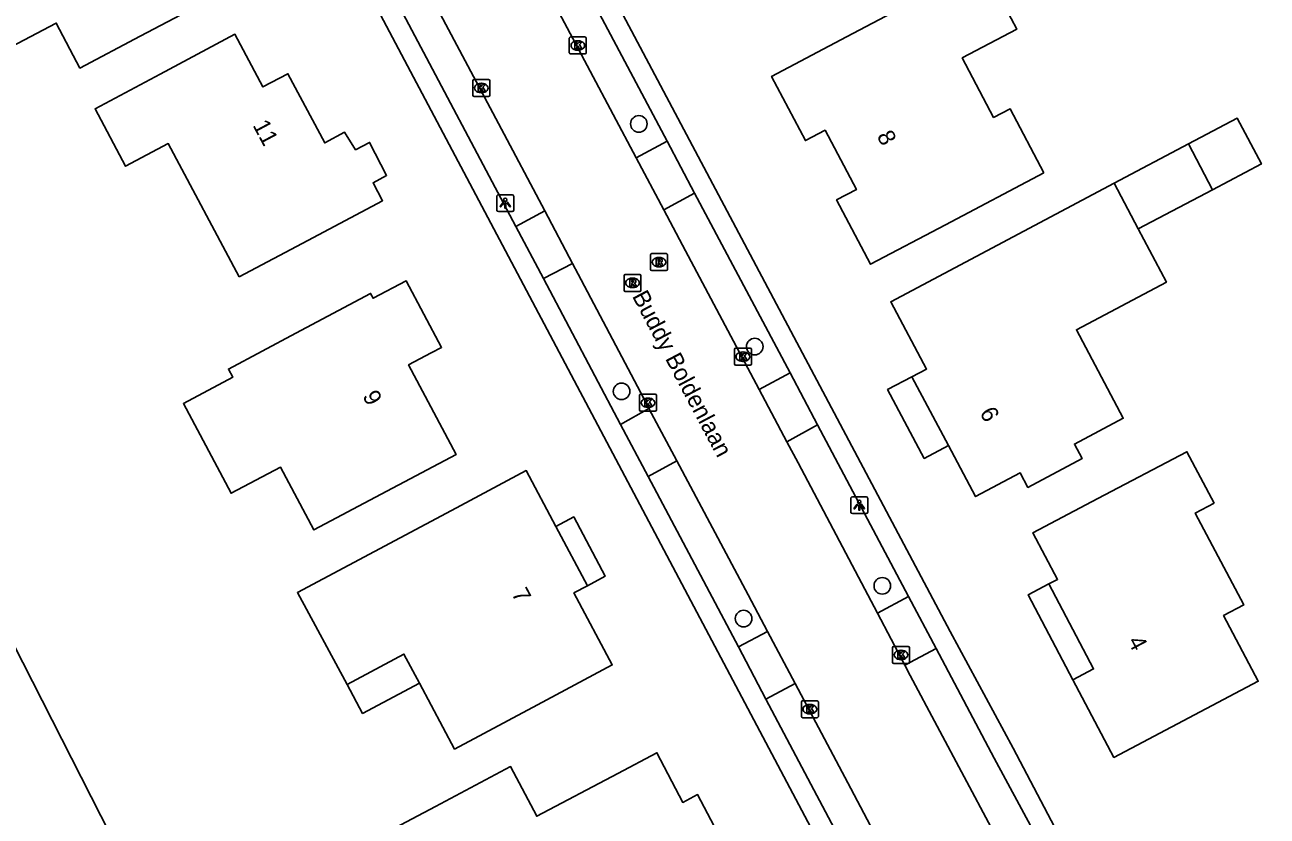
# Model space of a CAD drawing. Extents: x 160457 to 162082, y 388340 to 389736.
# Drawn here: x 160653.5 to 160726.7, y 389082.1 to 389128.7 of the extents above; entities that cross this region are included whole.
import ezdxf

# ---------------------------------------------------------------- set-up
doc = ezdxf.new("R2010")
doc.units = 0
for name, color, linetype in [('IMGEO_Boom', 7, 'Continuous'), ('IMGEO_Grasland_overig', 7, 'Continuous'), ('IMGEO_Hek', 7, 'Continuous'), ('IMGEO_Kolk', 7, 'Continuous'), ('IMGEO_Lichtpunt', 7, 'Continuous'), ('IMGEO_Openbare_ruimte_label', 7, 'Continuous'), ('IMGEO_Pand', 7, 'Continuous'), ('IMGEO_Pand_nummerreeks', 7, 'Continuous'), ('IMGEO_Pand_overbouw', 7, 'Continuous'), ('IMGEO_Rijbaan_lokaal_gesloten', 7, 'Continuous'), ('IMGEO_Rioolput', 7, 'Continuous'), ('IMGEO_Voetpad_open', 7, 'Continuous')]:
    doc.layers.add(name, color=color, linetype=linetype)

msp = doc.modelspace()

# ---------------------------------------------------------------- linework, layer by layer
at = {"layer": 'IMGEO_Boom'}
for centre in [(160689.681, 389122.893), (160696.514, 389109.757), (160688.66, 389107.12), (160704.034, 389095.651), (160695.854, 389093.718)]:
    msp.add_circle(centre, 0.489, dxfattribs=at)
at = {"layer": 'IMGEO_Grasland_overig'}
msp.add_lwpolyline([(160635.49, 389126.227), (160661.981, 389074.172), (160677.134, 389044.454)], dxfattribs=at)
at = {"layer": 'IMGEO_Hek'}
msp.add_lwpolyline([(160661.981, 389074.172), (160635.49, 389126.227), (160631.304, 389134.452)], dxfattribs=at)
at = {"layer": 'IMGEO_Kolk'}
for p, q in [((160685.58, 389127.091), (160685.58, 389127.943)), ((160685.655, 389128.017), (160686.507, 389128.017)), ((160686.068, 389127.797), (160686.093, 389127.797)), ((160686.581, 389127.943), (160686.581, 389127.091)), ((160686.507, 389127.017), (160685.655, 389127.017)), ((160686.091, 389127.237), (160686.066, 389127.237)), ((160679.891, 389124.581), (160679.891, 389125.433)), ((160679.966, 389125.507), (160680.818, 389125.507)), ((160680.892, 389125.433), (160680.892, 389124.581)), ((160680.402, 389124.727), (160680.377, 389124.727)), ((160680.379, 389125.287), (160680.404, 389125.287)), ((160680.818, 389124.507), (160679.966, 389124.507)), ((160695.314, 389108.738), (160695.314, 389109.59)), ((160695.389, 389109.664), (160696.241, 389109.664)), ((160695.802, 389109.444), (160695.827, 389109.444)), ((160696.315, 389109.59), (160696.315, 389108.738)), ((160696.241, 389108.664), (160695.389, 389108.664)), ((160695.825, 389108.884), (160695.8, 389108.884)), ((160689.716, 389106.021), (160689.716, 389106.873)), ((160689.791, 389106.947), (160690.643, 389106.947)), ((160690.204, 389106.727), (160690.229, 389106.727)), ((160690.717, 389106.873), (160690.717, 389106.021)), ((160690.643, 389105.947), (160689.791, 389105.947)), ((160690.227, 389106.167), (160690.202, 389106.167)), ((160704.638, 389091.15), (160704.638, 389092.002)), ((160704.713, 389092.076), (160705.565, 389092.076)), ((160705.126, 389091.856), (160705.151, 389091.856)), ((160705.639, 389092.002), (160705.639, 389091.15)), ((160705.565, 389091.076), (160704.713, 389091.076)), ((160705.149, 389091.296), (160705.124, 389091.296)), ((160699.263, 389087.949), (160699.263, 389088.801)), ((160699.338, 389088.875), (160700.19, 389088.875)), ((160700.264, 389088.801), (160700.264, 389087.949)), ((160699.774, 389088.095), (160699.749, 389088.095)), ((160699.751, 389088.655), (160699.776, 389088.655)), ((160700.19, 389087.875), (160699.338, 389087.875))]:
    msp.add_line(p, q, dxfattribs=at)
for points in [[(160685.58, 389127.091), (160685.58, 389127.943)], [(160685.655, 389128.017), (160686.507, 389128.017)], [(160685.901, 389127.717), (160686.024, 389127.717), (160686.024, 389127.566), (160686.154, 389127.717), (160686.318, 389127.717), (160686.172, 389127.566), (160686.325, 389127.317), (160686.173, 389127.317), (160686.088, 389127.481), (160686.024, 389127.414), (160686.024, 389127.317), (160685.901, 389127.317), (160685.901, 389127.717)], [(160686.581, 389127.943), (160686.581, 389127.091)], [(160686.507, 389127.017), (160685.655, 389127.017)], [(160679.891, 389124.581), (160679.891, 389125.433)], [(160679.966, 389125.507), (160680.818, 389125.507)], [(160680.892, 389125.433), (160680.892, 389124.581)], [(160680.212, 389125.207), (160680.335, 389125.207), (160680.335, 389125.056), (160680.465, 389125.207), (160680.629, 389125.207), (160680.483, 389125.056), (160680.636, 389124.807), (160680.484, 389124.807), (160680.399, 389124.971), (160680.335, 389124.904), (160680.335, 389124.807), (160680.212, 389124.807), (160680.212, 389125.207)], [(160680.818, 389124.507), (160679.966, 389124.507)], [(160695.314, 389108.738), (160695.314, 389109.59)], [(160695.389, 389109.664), (160696.241, 389109.664)], [(160695.635, 389109.364), (160695.758, 389109.364), (160695.758, 389109.213), (160695.888, 389109.364), (160696.052, 389109.364), (160695.906, 389109.213), (160696.059, 389108.964), (160695.907, 389108.964), (160695.822, 389109.128), (160695.758, 389109.061), (160695.758, 389108.964), (160695.635, 389108.964), (160695.635, 389109.364)], [(160696.315, 389109.59), (160696.315, 389108.738)], [(160696.241, 389108.664), (160695.389, 389108.664)], [(160689.716, 389106.021), (160689.716, 389106.873)], [(160689.791, 389106.947), (160690.643, 389106.947)], [(160690.037, 389106.647), (160690.16, 389106.647), (160690.16, 389106.496), (160690.29, 389106.647), (160690.454, 389106.647), (160690.308, 389106.496), (160690.461, 389106.247), (160690.309, 389106.247), (160690.224, 389106.411), (160690.16, 389106.344), (160690.16, 389106.247), (160690.037, 389106.247), (160690.037, 389106.647)], [(160690.717, 389106.873), (160690.717, 389106.021)], [(160690.643, 389105.947), (160689.791, 389105.947)], [(160704.638, 389091.15), (160704.638, 389092.002)], [(160704.713, 389092.076), (160705.565, 389092.076)], [(160704.959, 389091.776), (160705.082, 389091.776), (160705.082, 389091.625), (160705.212, 389091.776), (160705.376, 389091.776), (160705.23, 389091.625), (160705.383, 389091.376), (160705.231, 389091.376), (160705.146, 389091.54), (160705.082, 389091.473), (160705.082, 389091.376), (160704.959, 389091.376), (160704.959, 389091.776)], [(160705.639, 389092.002), (160705.639, 389091.15)], [(160705.565, 389091.076), (160704.713, 389091.076)], [(160699.263, 389087.949), (160699.263, 389088.801)], [(160699.338, 389088.875), (160700.19, 389088.875)], [(160700.264, 389088.801), (160700.264, 389087.949)], [(160699.584, 389088.575), (160699.707, 389088.575), (160699.707, 389088.424), (160699.837, 389088.575), (160700.001, 389088.575), (160699.855, 389088.424), (160700.008, 389088.175), (160699.856, 389088.175), (160699.771, 389088.339), (160699.707, 389088.272), (160699.707, 389088.175), (160699.584, 389088.175), (160699.584, 389088.575)], [(160700.19, 389087.875), (160699.338, 389087.875)]]:
    msp.add_lwpolyline(points, dxfattribs=at)
for centre, start, end in [((160685.657, 389127.941), 91.55205, 178.44795), ((160685.657, 389127.941), 91.55205, 178.44795), ((160686.505, 389127.941), 1.55205, 88.44795), ((160686.505, 389127.941), 1.55205, 88.44795), ((160685.657, 389127.093), 181.55205, 268.44795), ((160685.657, 389127.093), 181.55205, 268.44795), ((160686.505, 389127.093), 271.55205, 358.44795), ((160686.505, 389127.093), 271.55205, 358.44795), ((160679.968, 389125.431), 91.55205, 178.44795), ((160679.968, 389125.431), 91.55205, 178.44795), ((160680.816, 389125.431), 1.55205, 88.44795), ((160680.816, 389125.431), 1.55205, 88.44795), ((160679.968, 389124.583), 181.55205, 268.44795), ((160679.968, 389124.583), 181.55205, 268.44795), ((160680.816, 389124.583), 271.55205, 358.44795), ((160680.816, 389124.583), 271.55205, 358.44795), ((160695.391, 389109.588), 91.55205, 178.44795), ((160695.391, 389109.588), 91.55205, 178.44795), ((160696.239, 389109.588), 1.55205, 88.44795), ((160696.239, 389109.588), 1.55205, 88.44795), ((160695.391, 389108.74), 181.55205, 268.44795), ((160695.391, 389108.74), 181.55205, 268.44795), ((160696.239, 389108.74), 271.55205, 358.44795), ((160696.239, 389108.74), 271.55205, 358.44795), ((160689.793, 389106.871), 91.55205, 178.44795), ((160689.793, 389106.871), 91.55205, 178.44795), ((160690.641, 389106.871), 1.55205, 88.44795), ((160690.641, 389106.871), 1.55205, 88.44795), ((160689.793, 389106.023), 181.55205, 268.44795), ((160689.793, 389106.023), 181.55205, 268.44795), ((160690.641, 389106.023), 271.55205, 358.44795), ((160690.641, 389106.023), 271.55205, 358.44795), ((160704.715, 389092), 91.55205, 178.44795), ((160704.715, 389092), 91.55205, 178.44795), ((160705.563, 389092), 1.55205, 88.44795), ((160705.563, 389092), 1.55205, 88.44795), ((160704.715, 389091.152), 181.55205, 268.44795), ((160704.715, 389091.152), 181.55205, 268.44795), ((160705.563, 389091.152), 271.55205, 358.44795), ((160705.563, 389091.152), 271.55205, 358.44795), ((160699.34, 389088.799), 91.55205, 178.44795), ((160699.34, 389088.799), 91.55205, 178.44795), ((160700.188, 389088.799), 1.55205, 88.44795), ((160700.188, 389088.799), 1.55205, 88.44795), ((160699.34, 389087.951), 181.55205, 268.44795), ((160699.34, 389087.951), 181.55205, 268.44795), ((160700.188, 389087.951), 271.55205, 358.44795), ((160700.188, 389087.951), 271.55205, 358.44795)]:
    msp.add_arc(centre, 0.0765, start, end, dxfattribs=at)
for centre, major_axis, ratio, start_param, end_param in [((160686.067, 389127.517), (-0.387, 0.002), 0.722429, 4.712389, 7.853982), ((160686.092, 389127.517), (-0.39, 0.002), 0.717154, 1.570796, 4.712389), ((160680.378, 389125.007), (-0.387, 0.002), 0.722429, 4.712389, 7.853982), ((160680.403, 389125.007), (-0.39, 0.002), 0.717154, 1.570796, 4.712389), ((160695.801, 389109.164), (-0.387, 0.002), 0.722429, 4.712389, 7.853982), ((160695.826, 389109.164), (-0.39, 0.002), 0.717154, 1.570796, 4.712389), ((160690.203, 389106.447), (-0.387, 0.002), 0.722429, 4.712389, 7.853982), ((160690.228, 389106.447), (-0.39, 0.002), 0.717154, 1.570796, 4.712389), ((160705.125, 389091.576), (-0.387, 0.002), 0.722429, 4.712389, 7.853982), ((160705.15, 389091.576), (-0.39, 0.002), 0.717154, 1.570796, 4.712389), ((160699.75, 389088.375), (-0.387, 0.002), 0.722429, 4.712389, 7.853982), ((160699.775, 389088.375), (-0.39, 0.002), 0.717154, 1.570796, 4.712389)]:
    msp.add_ellipse(centre, major_axis=major_axis, ratio=ratio, start_param=start_param, end_param=end_param, dxfattribs=at)
at = {"layer": 'IMGEO_Lichtpunt'}
for p, q in [((160681.307, 389118.62), (160681.307, 389117.813)), ((160681.307, 389118.62), (160681.307, 389117.813)), ((160682.209, 389118.715), (160681.401, 389118.715)), ((160682.209, 389118.715), (160681.401, 389118.715)), ((160682.303, 389117.813), (160682.303, 389118.62)), ((160682.303, 389117.813), (160682.303, 389118.62)), ((160681.401, 389117.719), (160682.209, 389117.719)), ((160681.401, 389117.719), (160682.209, 389117.719)), ((160702.177, 389100.81), (160702.177, 389100.003)), ((160702.177, 389100.81), (160702.177, 389100.003)), ((160703.079, 389100.905), (160702.271, 389100.905)), ((160703.079, 389100.905), (160702.271, 389100.905)), ((160703.173, 389100.003), (160703.173, 389100.81)), ((160703.173, 389100.003), (160703.173, 389100.81)), ((160702.271, 389099.909), (160703.079, 389099.909)), ((160702.271, 389099.909), (160703.079, 389099.909))]:
    msp.add_line(p, q, dxfattribs=at)
for points in [[(160681.681, 389118.284), (160681.72, 389118.256), (160681.532, 389117.994), (160681.494, 389118.021), (160681.681, 389118.284)], [(160681.783, 389118.236), (160681.83, 389118.236), (160681.83, 389117.914), (160681.783, 389117.914), (160681.783, 389118.236)], [(160681.893, 389118.256), (160681.931, 389118.283), (160682.118, 389118.021), (160682.079, 389117.993), (160681.893, 389118.256)], [(160702.551, 389100.474), (160702.59, 389100.446), (160702.402, 389100.184), (160702.364, 389100.211), (160702.551, 389100.474)], [(160702.653, 389100.426), (160702.7, 389100.426), (160702.7, 389100.104), (160702.653, 389100.104), (160702.653, 389100.426)], [(160702.763, 389100.446), (160702.801, 389100.473), (160702.988, 389100.211), (160702.949, 389100.183), (160702.763, 389100.446)]]:
    msp.add_lwpolyline(points, dxfattribs=at)
for centre in [(160681.806, 389118.418), (160702.676, 389100.608)]:
    msp.add_circle(centre, 0.0994, dxfattribs=at)
for centre, start, end in [((160681.401, 389118.62), 90, 180), ((160681.401, 389118.62), 90, 180), ((160682.209, 389118.62), 0, 90), ((160682.209, 389118.62), 0, 90), ((160681.401, 389117.813), 180, 270), ((160681.401, 389117.813), 180, 270), ((160682.209, 389117.813), 270, 0), ((160682.209, 389117.813), 270, 360), ((160702.271, 389100.81), 90, 180), ((160702.271, 389100.81), 90, 180), ((160703.079, 389100.81), 0, 90), ((160703.079, 389100.81), 0, 90), ((160702.271, 389100.003), 180, 270), ((160702.271, 389100.003), 180, 270), ((160703.079, 389100.003), 270, 0), ((160703.079, 389100.003), 270, 360)]:
    msp.add_arc(centre, 0.0946, start, end, dxfattribs=at)
at = {"layer": 'IMGEO_Pand'}
for points in [[(160660.27, 389128.061), (160656.728, 389126.188), (160655.325, 389128.842), (160652.662, 389127.434), (160649.853, 389132.76), (160652.51, 389134.163), (160651.112, 389136.811), (160654.723, 389138.709), (160659.148, 389141.035), (160660.519, 389138.399), (160661.395, 389138.854), (160661.941, 389137.804), (160662.817, 389138.259), (160664.495, 389135.049), (160663.61, 389134.581), (160664.172, 389133.52), (160663.287, 389133.052), (160664.69, 389130.398), (160660.27, 389128.061)], [(160713.566, 389120.001), (160707.766, 389116.943), (160703.343, 389114.61), (160701.342, 389118.412), (160702.503, 389119.023), (160700.665, 389122.514), (160699.504, 389121.903), (160697.508, 389125.696), (160701.931, 389128.029), (160709.961, 389132.263), (160711.959, 389128.475), (160708.746, 389126.781), (160710.594, 389123.276), (160711.568, 389123.789), (160713.566, 389120.001)], [(160666.113, 389113.864), (160661.93, 389121.73), (160659.42, 389120.395), (160657.616, 389123.789), (160661.449, 389125.829), (160665.863, 389128.177), (160667.515, 389125.071), (160668.984, 389125.853), (160671.165, 389121.774), (160672.332, 389122.398), (160672.982, 389121.368), (160673.804, 389121.8), (160674.811, 389119.849), (160674.007, 389119.421), (160674.571, 389118.361), (160670.157, 389116.014), (160666.113, 389113.864)], [(160722.087, 389121.707), (160724.96, 389123.227), (160726.39, 389120.534), (160723.511, 389119.013)], [(160722.087, 389121.707), (160717.698, 389119.387)], [(160723.511, 389119.013), (160722.087, 389121.707)], [(160717.698, 389119.387), (160708.947, 389114.744), (160704.53, 389112.4), (160706.648, 389108.435), (160705.78, 389107.971), (160707.94, 389103.917), (160709.538, 389100.917), (160712.166, 389102.312), (160712.62, 389101.456), (160715.814, 389103.15), (160715.359, 389104.006), (160718.243, 389105.536), (160715.477, 389110.749), (160720.787, 389113.566), (160719.127, 389116.694)], [(160719.127, 389116.694), (160717.698, 389119.387)], [(160719.127, 389116.694), (160723.511, 389119.013)], [(160674.495, 389101.056), (160670.521, 389098.945), (160668.551, 389102.654), (160665.637, 389101.106), (160662.823, 389106.402), (160665.736, 389107.95), (160665.478, 389108.435), (160669.449, 389110.545), (160673.864, 389112.89), (160674.014, 389112.607), (160675.956, 389113.639), (160678.048, 389109.713), (160677.437, 389109.388), (160676.105, 389108.681), (160678.91, 389103.401), (160674.495, 389101.056)], [(160723.597, 389100.53), (160722.482, 389099.942), (160725.341, 389094.525), (160724.155, 389093.899), (160726.202, 389090.023), (160722.11, 389087.863), (160717.688, 389085.528), (160715.276, 389090.111), (160716.494, 389090.753), (160713.855, 389095.761), (160714.369, 389096.033), (160712.915, 389098.784), (160716.742, 389100.795), (160721.999, 389103.557), (160723.597, 389100.53)], [(160678.632, 389100.096), (160683.042, 389102.451), (160684.795, 389099.151), (160686.649, 389095.66), (160685.848, 389095.232), (160688.114, 389090.988), (160683.703, 389088.635), (160678.813, 389086.026), (160676.74, 389089.912), (160675.828, 389091.621), (160672.475, 389089.832), (160669.553, 389095.248), (160678.632, 389100.096)], [(160688.447, 389084.586), (160690.743, 389085.803), (160692.268, 389082.875), (160693.145, 389083.341), (160695.329, 389079.201), (160694.457, 389078.736), (160694.701, 389078.278), (160690.074, 389075.811), (160690.497, 389075.017), (160686.752, 389073.02), (160684.557, 389077.136), (160681.819, 389075.676), (160681.491, 389075.501), (160680.274, 389077.783), (160674.114, 389074.499), (160671.515, 389079.372), (160677.681, 389082.639), (160682.122, 389084.991), (160683.661, 389082.063), (160688.447, 389084.586)]]:
    msp.add_lwpolyline(points, dxfattribs=at)
at = {"layer": 'IMGEO_Pand_overbouw'}
for points in [[(160705.78, 389107.971), (160704.341, 389107.222), (160706.507, 389103.163), (160707.94, 389103.917)], [(160686.649, 389095.66), (160687.696, 389096.225), (160685.842, 389099.714), (160684.795, 389099.151)], [(160713.855, 389095.761), (160712.63, 389095.113), (160715.276, 389090.111), (160716.494, 389090.753)], [(160672.475, 389089.832), (160673.395, 389088.128), (160676.74, 389089.912), (160675.828, 389091.621)]]:
    msp.add_lwpolyline(points, close=True, dxfattribs=at)
at = {"layer": 'IMGEO_Rijbaan_lokaal_gesloten'}
for points in [[(160689.524, 389120.887), (160685.454, 389128.559), (160683.343, 389132.534)], [(160677.483, 389130.318), (160681.399, 389122.914), (160684.135, 389117.759)], [(160691.147, 389117.827), (160689.524, 389120.887)], [(160684.135, 389117.759), (160685.776, 389114.667)], [(160696.77, 389107.223), (160692.251, 389115.746), (160691.147, 389117.827)], [(160685.776, 389114.667), (160686.111, 389114.036), (160689.973, 389106.689), (160690.278, 389106.114)], [(160698.403, 389104.144), (160696.77, 389107.223)], [(160690.278, 389106.114), (160691.923, 389103.017)], [(160703.743, 389094.037), (160699.064, 389102.897), (160698.403, 389104.144)], [(160691.923, 389103.017), (160696.121, 389095.113), (160697.262, 389092.96)], [(160705.359, 389090.978), (160703.743, 389094.037)], [(160697.262, 389092.96), (160698.893, 389089.881)], [(160722.882, 389056.293), (160719.266, 389063.633), (160714.398, 389073.548), (160711.825, 389078.763), (160710.449, 389081.399), (160705.683, 389090.365), (160705.359, 389090.978)], [(160698.893, 389089.881), (160702.17, 389083.695), (160705.064, 389078.212)]]:
    msp.add_lwpolyline(points, dxfattribs=at)
at = {"layer": 'IMGEO_Rioolput'}
for p, q in [((160690.366, 389114.314), (160690.366, 389115.166)), ((160690.441, 389115.24), (160691.293, 389115.24)), ((160691.367, 389115.166), (160691.367, 389114.314)), ((160690.877, 389114.46), (160690.852, 389114.46)), ((160690.854, 389115.02), (160690.879, 389115.02)), ((160688.805, 389113.089), (160688.805, 389113.941)), ((160688.88, 389114.015), (160689.732, 389114.015)), ((160689.293, 389113.795), (160689.318, 389113.795)), ((160689.806, 389113.941), (160689.806, 389113.089)), ((160691.293, 389114.24), (160690.441, 389114.24)), ((160689.732, 389113.015), (160688.88, 389113.015)), ((160689.316, 389113.235), (160689.291, 389113.235))]:
    msp.add_line(p, q, dxfattribs=at)
for points in [[(160690.366, 389114.314), (160690.366, 389115.166)], [(160690.441, 389115.24), (160691.293, 389115.24)], [(160691.367, 389115.166), (160691.367, 389114.314)], [(160690.955, 389114.938), (160690.703, 389114.94), (160690.703, 389114.54)], [(160690.703, 389114.54), (160690.827, 389114.54), (160690.827, 389114.702), (160690.838, 389114.702)], [(160690.881, 389114.859), (160690.827, 389114.859), (160690.827, 389114.778)], [(160690.827, 389114.778), (160690.879, 389114.778)], [(160690.885, 389114.673), (160690.956, 389114.54), (160691.096, 389114.54), (160691.031, 389114.666)], [(160688.805, 389113.089), (160688.805, 389113.941)], [(160688.88, 389114.015), (160689.732, 389114.015)], [(160689.394, 389113.713), (160689.142, 389113.715), (160689.142, 389113.315)], [(160689.806, 389113.941), (160689.806, 389113.089)], [(160691.293, 389114.24), (160690.441, 389114.24)], [(160689.732, 389113.015), (160688.88, 389113.015)], [(160689.142, 389113.315), (160689.266, 389113.315), (160689.266, 389113.477), (160689.277, 389113.477)], [(160689.32, 389113.634), (160689.266, 389113.634), (160689.266, 389113.553)], [(160689.266, 389113.553), (160689.318, 389113.553)], [(160689.324, 389113.448), (160689.395, 389113.315), (160689.535, 389113.315), (160689.47, 389113.441)]]:
    msp.add_lwpolyline(points, dxfattribs=at)
for centre, radius, start, end in [((160690.443, 389115.164), 0.0765, 91.55205, 178.44795), ((160690.443, 389115.164), 0.0765, 91.55205, 178.44795), ((160691.291, 389115.164), 0.0765, 1.55205, 88.44795), ((160691.291, 389115.164), 0.0765, 1.55205, 88.44795), ((160690.837, 389114.649), 0.0533, 26.02933, 88.69889), ((160690.863, 389114.967), 0.19, 274.7715, 282.96867), ((160690.887, 389114.763), 0.0964, 77.00612, 93.18647), ((160690.901, 389114.82), 0.0378, 276.66336, 79.67722), ((160690.954, 389114.828), 0.109, 350.36119, 89.41601), ((160690.952, 389114.828), 0.112, 277.58423, 350.98172), ((160690.936, 389114.613), 0.108, 29.51342, 73.79051), ((160688.882, 389113.939), 0.0765, 91.55205, 178.44795), ((160688.882, 389113.939), 0.0765, 91.55205, 178.44795), ((160689.393, 389113.603), 0.109, 350.36119, 89.41601), ((160689.73, 389113.939), 0.0765, 1.55205, 88.44795), ((160689.73, 389113.939), 0.0765, 1.55205, 88.44795), ((160690.443, 389114.316), 0.0765, 181.55205, 268.44795), ((160690.443, 389114.316), 0.0765, 181.55205, 268.44795), ((160691.291, 389114.316), 0.0765, 271.55205, 358.44795), ((160691.291, 389114.316), 0.0765, 271.55205, 358.44795), ((160688.882, 389113.091), 0.0765, 181.55205, 268.44795), ((160688.882, 389113.091), 0.0765, 181.55205, 268.44795), ((160689.276, 389113.424), 0.0533, 26.02933, 88.69889), ((160689.302, 389113.742), 0.19, 274.7715, 282.96867), ((160689.326, 389113.538), 0.0964, 77.00612, 93.18647), ((160689.34, 389113.595), 0.0378, 276.66336, 79.67722), ((160689.391, 389113.603), 0.112, 277.58423, 350.98172), ((160689.375, 389113.388), 0.108, 29.51342, 73.79051), ((160689.73, 389113.091), 0.0765, 271.55205, 358.44795), ((160689.73, 389113.091), 0.0765, 271.55205, 358.44795)]:
    msp.add_arc(centre, radius, start, end, dxfattribs=at)
for centre, major_axis, ratio, start_param, end_param in [((160690.853, 389114.74), (-0.387, 0.002), 0.722429, 4.712389, 7.853982), ((160690.878, 389114.74), (-0.39, 0.002), 0.717154, 1.570796, 4.712389), ((160689.292, 389113.515), (-0.387, 0.002), 0.722429, 4.712389, 7.853982), ((160689.317, 389113.515), (-0.39, 0.002), 0.717154, 1.570796, 4.712389)]:
    msp.add_ellipse(centre, major_axis=major_axis, ratio=ratio, start_param=start_param, end_param=end_param, dxfattribs=at)
at = {"layer": 'IMGEO_Voetpad_open'}
for points in [[(160666.197, 389171.948), (160666.685, 389171.014), (160676.789, 389151.881), (160708.027, 389092.962), (160711.74, 389086.082), (160713.992, 389081.813), (160714.548, 389080.749), (160722.246, 389065.089), (160725.803, 389057.769), (160726.725, 389055.856)], [(160715.497, 389049.443), (160715.59, 389049.493), (160705.696, 389069.922), (160703.712, 389073.937), (160701.581, 389078.055), (160687.433, 389104.792), (160673.051, 389131.978), (160665.928, 389145.4), (160655.489, 389165.053), (160655.393, 389165.23)], [(160691.351, 389121.867), (160685.179, 389133.511)], [(160675.769, 389129.425), (160682.426, 389116.839)], [(160691.351, 389121.867), (160689.524, 389120.887)], [(160692.969, 389118.801), (160691.351, 389121.867)], [(160692.969, 389118.801), (160691.147, 389117.827)], [(160698.593, 389108.215), (160692.969, 389118.801)], [(160682.426, 389116.839), (160684.135, 389117.759)], [(160682.426, 389116.839), (160684.057, 389113.77)], [(160684.057, 389113.77), (160685.776, 389114.667)], [(160684.057, 389113.77), (160688.598, 389105.17)], [(160698.593, 389108.215), (160696.77, 389107.223)], [(160700.213, 389105.136), (160698.593, 389108.215)], [(160688.598, 389105.17), (160690.278, 389106.114)], [(160688.598, 389105.17), (160690.236, 389102.105)], [(160700.213, 389105.136), (160698.403, 389104.144)], [(160705.574, 389095.015), (160700.213, 389105.136)], [(160690.236, 389102.105), (160691.923, 389103.017)], [(160690.236, 389102.105), (160695.556, 389092.056)], [(160705.574, 389095.015), (160703.743, 389094.037)], [(160707.206, 389091.946), (160705.574, 389095.015)], [(160695.556, 389092.056), (160697.262, 389092.96)], [(160695.556, 389092.056), (160697.171, 389088.966)], [(160707.206, 389091.946), (160705.359, 389090.978)], [(160722.882, 389056.293), (160724.711, 389057.228), (160721.194, 389064.425), (160713.435, 389080.182), (160712.901, 389081.257), (160710.623, 389085.496), (160707.206, 389091.946)], [(160697.171, 389088.966), (160698.893, 389089.881)], [(160697.171, 389088.966), (160703.333, 389077.308)]]:
    msp.add_lwpolyline(points, dxfattribs=at)

# ---------------------------------------------------------------- texts
at = {"layer": 'IMGEO_Openbare_ruimte_label'}
msp.add_text('Buddy Boldenlaan', height=1, rotation=297.89727, dxfattribs=at).set_placement((160689.261, 389112.737))
at = {"layer": 'IMGEO_Pand_nummerreeks'}
for s, rotation, p in [('11', 298.13296, (160666.889, 389122.815)), ('8', 297.76666, (160703.688, 389122.183)), ('9', 298.00287, (160673.362, 389106.849)), ('6', 298.04607, (160709.753, 389105.872)), ('7', 298.09764, (160682.147, 389095.201)), ('4', 297.78824, (160718.482, 389092.385))]:
    msp.add_text(s, height=1, rotation=rotation, dxfattribs=at).set_placement(p)

doc.saveas('drawing.dxf')
